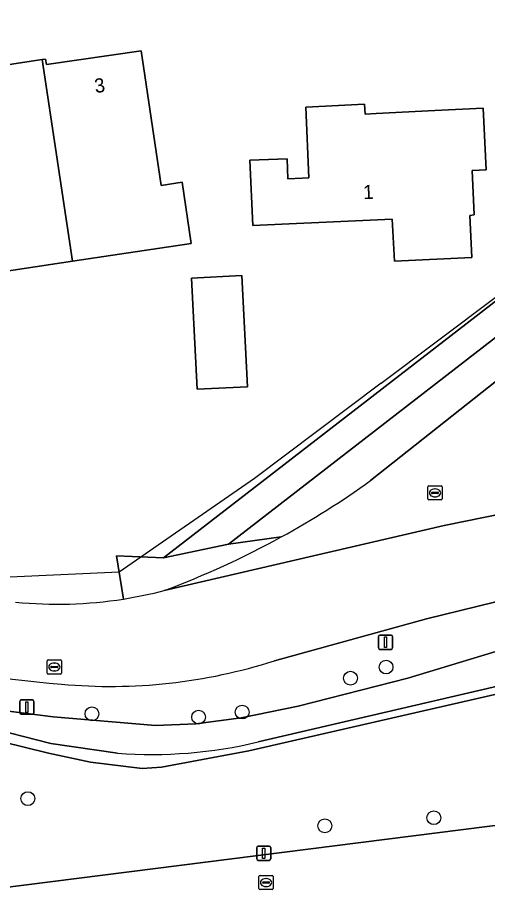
# Model space of a CAD drawing. Extents: x 162156 to 163172, y 378995 to 380779.
# Drawn here: x 162299.8 to 162333, y 380168.4 to 380231 of the extents above; entities that cross this region are included whole.
import ezdxf

# ---------------------------------------------------------------- set-up
doc = ezdxf.new("R2010")
doc.units = 0
for name, color, linetype in [('IMGEO_Boom', 7, 'Continuous'), ('IMGEO_Erf', 7, 'Continuous'), ('IMGEO_Groenvoorziening', 7, 'Continuous'), ('IMGEO_Hek', 7, 'Continuous'), ('IMGEO_Lichtmast', 7, 'Continuous'), ('IMGEO_Pand', 7, 'Continuous'), ('IMGEO_Pand_nummerreeks', 7, 'Continuous'), ('IMGEO_Rijbaan_lokaal_gesloten', 7, 'Continuous'), ('IMGEO_Rioolput', 7, 'Continuous'), ('IMGEO_Waterleidingput', 7, 'Continuous'), ('IMGEO_Waterloop', 7, 'Continuous')]:
    doc.layers.add(name, color=color, linetype=linetype)

msp = doc.modelspace()

# ---------------------------------------------------------------- linework, layer by layer
at = {"layer": 'IMGEO_Boom'}
for centre in [(162325.875, 380185.02), (162323.363, 380184.23), (162315.697, 380181.835), (162305.068, 380181.713), (162312.617, 380181.479), (162300.532, 380175.71), (162329.255, 380174.358), (162321.541, 380173.789)]:
    msp.add_circle(centre, 0.489, dxfattribs=at)
at = {"layer": 'IMGEO_Erf'}
for points in [[(162312.1, 380214.998), (162303.688, 380213.74), (162295.276, 380212.481), (162295.656, 380210.025), (162292.642, 380209.57), (162291.834, 380211.745), (162291.4, 380214.642), (162294.812, 380215.154), (162294.564, 380216.805), (162296.097, 380217.035), (162294.609, 380226.964), (162301.556, 380228.006), (162301.776, 380228.039), (162301.848, 380227.66), (162308.548, 380228.625), (162309.976, 380219.109), (162311.451, 380219.324)], [(162332.743, 380224.57), (162332.957, 380220.211), (162331.959, 380220.152), (162332.109, 380217.012), (162331.794, 380216.986), (162331.938, 380214.003), (162326.468, 380213.736), (162326.316, 380216.719), (162320.607, 380216.458), (162320.057, 380216.433), (162316.451, 380216.268), (162316.24, 380220.882), (162318.877, 380220.989), (162318.935, 380219.576), (162319.932, 380219.625), (162320.423, 380219.649), (162320.19, 380224.653), (162324.353, 380224.847), (162324.39, 380224.148), (162325.178, 380224.189), (162329.327, 380224.408)], [(162315.683, 380212.727), (162316.079, 380204.852), (162312.512, 380204.679), (162312.117, 380212.539)]]:
    msp.add_lwpolyline(points, close=True, dxfattribs=at)
msp.add_lwpolyline([(162307.295, 380189.835), (162306.81, 380192.901), (162310.127, 380192.76), (162353.115, 380225.997)], dxfattribs=at)
msp.add_arc((162302.622, 380219.443), 29.974, 264.33401, 278.96829, dxfattribs=at)
at = {"layer": 'IMGEO_Groenvoorziening'}
for points in [[(162354.159, 380226.783), (162353.115, 380225.997), (162310.127, 380192.76), (162314.733, 380193.715), (162354.477, 380224.489)], [(162354.477, 380224.489), (162314.733, 380193.715), (162318.467, 380194.227)], [(162324.772, 380198.212), (162340.006, 380210.284)], [(162318.467, 380194.227), (162314.733, 380193.715), (162310.127, 380192.76), (162306.81, 380192.901), (162307.295, 380189.835)], [(162408.085, 379703.181), (162408.289, 379704.226), (162408.362, 379710.922), (162407.433, 379718.658), (162402.674, 379750), (162400.562, 379766.602), (162399.53, 379777.438), (162398.595, 379783.512), (162394.073, 379815.929), (162388.914, 379854.445), (162387.247, 379866.948), (162383.975, 379890.989), (162369.543, 380000.044), (162352.327, 380129.869), (162352.7, 380129.905), (162350.587, 380145.671), (162344.822, 380188.69), (162344.718, 380189.464), (162342.565, 380189.181), (162342.118, 380191.718), (162328.735, 380188.436), (162317.977, 380185.472)], [(162289.203, 380186.217), (162277.89, 380189.107), (162278.442, 380184.1), (162278.772, 380184.135), (162278.757, 380184.272), (162292.3, 380181.3), (162302.003, 380178.939), (162304.976, 380178.29), (162308.611, 380177.854), (162309.981, 380177.927), (162316.172, 380179.083), (162342.217, 380185.053), (162346.322, 380153.311), (162346.539, 380151.632), (162347.441, 380145.205), (162349.391, 380131.315), (162352.731, 380105.568), (162366.947, 380000), (162368.464, 379988.666), (162368.623, 379987.477), (162371.684, 379964.606), (162386.534, 379853.639)], [(162306.872, 380178.924), (162302.171, 380179.61), (162297.351, 380180.835), (162290.271, 380182.222), (162278.755, 380184.863), (162279.04, 380186.519), (162289.844, 380183.552), (162297.843, 380182.07), (162302.338, 380181.506), (162309.559, 380180.888), (162312.416, 380181.003), (162315.635, 380181.426), (162319.666, 380182.264), (162327.408, 380184.242), (162341.185, 380188.417), (162341.57, 380185.476), (162316.835, 380179.72)]]:
    msp.add_lwpolyline(points, dxfattribs=at)
for points in [[(162338.626, 380174.447), (162341.504, 380153.008), (162346.322, 380153.311), (162342.217, 380185.053), (162316.172, 380179.083), (162309.981, 380177.927), (162308.611, 380177.854), (162304.976, 380178.29), (162302.003, 380178.939), (162292.3, 380181.3), (162278.757, 380184.272), (162278.772, 380184.135), (162280.517, 380167.715), (162235.526, 380161.77), (162231.086, 380161.186), (162231.132, 380160.825)], [(162347.875, 380105.55), (162341.504, 380153.008), (162338.626, 380174.447), (162231.132, 380160.825), (162234.006, 380138.54), (162234.545, 380138.605), (162235.45, 380138.742), (162239.5, 380111.988), (162238.595, 380111.851), (162237.47, 380111.681), (162239.093, 380099.095), (162240.095, 380091.317)]]:
    msp.add_lwpolyline(points, close=True, dxfattribs=at)
for centre, radius, start, end in [((162288.785, 380248.17), 61.57, 298.82183, 305.76706), ((162288.704, 380248.343), 61.76, 290.34479, 298.81046), ((162302.737, 380218.937), 29.456, 278.90108, 284.62756), ((162308.907, 380258.278), 74.706, 254.70699, 265.40243), ((162306.417, 380221.209), 37.56, 264.65655, 287.92526), ((162309.28, 380211.527), 32.692, 265.77515, 283.36081)]:
    msp.add_arc(centre, radius, start, end, dxfattribs=at)
at = {"layer": 'IMGEO_Hek'}
for points in [[(162325.53, 380205.107), (162353.989, 380226.515)], [(162325.53, 380205.107), (162316.565, 380198.358), (162306.984, 380191.725), (162299.257, 380191.374), (162294.601, 380191.534), (162271.637, 380197.316)], [(162342.217, 380185.053), (162316.172, 380179.083), (162309.981, 380177.927), (162308.611, 380177.854), (162304.976, 380178.29), (162302.003, 380178.939), (162292.3, 380181.3)]]:
    msp.add_lwpolyline(points, dxfattribs=at)
at = {"layer": 'IMGEO_Lichtmast'}
for p, q in [((162325.437, 380187.275), (162326.227, 380187.275)), ((162326.227, 380187.275), (162325.437, 380187.275)), ((162325.337, 380186.375), (162325.337, 380187.175)), ((162325.337, 380187.175), (162325.337, 380186.375)), ((162326.327, 380187.175), (162326.327, 380186.375)), ((162326.327, 380186.375), (162326.327, 380187.175)), ((162326.227, 380186.275), (162325.437, 380186.275)), ((162325.437, 380186.275), (162326.227, 380186.275)), ((162299.972, 380181.791), (162299.972, 380182.591)), ((162299.972, 380182.591), (162299.972, 380181.791)), ((162300.072, 380182.691), (162300.862, 380182.691)), ((162300.862, 380182.691), (162300.072, 380182.691)), ((162300.962, 380182.591), (162300.962, 380181.791)), ((162300.962, 380181.791), (162300.962, 380182.591)), ((162300.862, 380181.691), (162300.072, 380181.691)), ((162300.072, 380181.691), (162300.862, 380181.691)), ((162316.727, 380171.441), (162316.727, 380172.241)), ((162316.727, 380172.241), (162316.727, 380171.441)), ((162316.827, 380172.341), (162317.617, 380172.341)), ((162317.617, 380172.341), (162316.827, 380172.341)), ((162317.717, 380172.241), (162317.717, 380171.441)), ((162317.717, 380171.441), (162317.717, 380172.241)), ((162317.617, 380171.341), (162316.827, 380171.341)), ((162316.827, 380171.341), (162317.617, 380171.341))]:
    msp.add_line(p, q, dxfattribs=at)
for points in [[(162325.757, 380187.15), (162325.907, 380187.15), (162325.907, 380186.4), (162325.757, 380186.4), (162325.757, 380187.15)], [(162300.392, 380182.566), (162300.542, 380182.566), (162300.542, 380181.816), (162300.392, 380181.816), (162300.392, 380182.566)], [(162317.147, 380172.216), (162317.297, 380172.216), (162317.297, 380171.466), (162317.147, 380171.466), (162317.147, 380172.216)]]:
    msp.add_lwpolyline(points, dxfattribs=at)
for centre, start, end in [((162325.437, 380187.175), 90, 180), ((162325.437, 380187.175), 90, 180), ((162326.227, 380187.175), 0, 90), ((162326.227, 380187.175), 360, 90), ((162325.437, 380186.375), 180, 270), ((162325.437, 380186.375), 180, 270), ((162326.227, 380186.375), 270, 0), ((162326.227, 380186.375), 270, 0), ((162300.072, 380182.591), 90, 180), ((162300.072, 380182.591), 90, 180), ((162300.862, 380182.591), 0, 90), ((162300.862, 380182.591), 360, 90), ((162300.072, 380181.791), 180, 270), ((162300.072, 380181.791), 180, 270), ((162300.862, 380181.791), 270, 0), ((162300.862, 380181.791), 270, 0), ((162316.827, 380172.241), 90, 180), ((162316.827, 380172.241), 90, 180), ((162317.617, 380172.241), 0, 90), ((162317.617, 380172.241), 360, 90), ((162316.827, 380171.441), 180, 270), ((162316.827, 380171.441), 180, 270), ((162317.617, 380171.441), 270, 0), ((162317.617, 380171.441), 270, 0)]:
    msp.add_arc(centre, 0.1, start, end, dxfattribs=at)
at = {"layer": 'IMGEO_Pand'}
for points in [[(162301.556, 380228.006), (162303.688, 380213.74), (162312.1, 380214.998), (162311.451, 380219.324), (162309.976, 380219.109), (162308.548, 380228.625), (162301.848, 380227.66), (162301.776, 380228.039)], [(162301.556, 380228.006), (162294.609, 380226.964), (162296.097, 380217.035), (162294.564, 380216.805), (162294.812, 380215.154), (162291.4, 380214.642), (162291.834, 380211.745), (162292.642, 380209.57), (162295.656, 380210.025), (162295.276, 380212.481), (162303.688, 380213.74)], [(162331.959, 380220.152), (162332.957, 380220.211), (162332.743, 380224.57), (162329.327, 380224.408), (162325.178, 380224.189), (162324.39, 380224.148), (162324.353, 380224.847), (162320.19, 380224.653), (162320.423, 380219.649), (162319.932, 380219.625), (162318.935, 380219.576), (162318.877, 380220.989), (162316.24, 380220.882), (162316.451, 380216.268), (162320.057, 380216.433), (162320.607, 380216.458), (162326.316, 380216.719), (162326.468, 380213.736), (162331.938, 380214.003), (162331.794, 380216.986), (162332.109, 380217.012)], [(162315.683, 380212.727), (162312.117, 380212.539), (162312.512, 380204.679), (162316.079, 380204.852)]]:
    msp.add_lwpolyline(points, close=True, dxfattribs=at)
at = {"layer": 'IMGEO_Rijbaan_lokaal_gesloten'}
for points in [[(162381.999, 380241.493), (162372.733, 380234.326), (162366.037, 380229.487), (162365.645, 380229.204), (162358.695, 380224.728), (162358.331, 380224.494), (162353.288, 380221.289), (162343.433, 380213.084), (162340.006, 380210.284), (162324.772, 380198.212)], [(162310.176, 380190.435), (162329.976, 380195.039), (162345.414, 380198.175), (162349.145, 380198.355), (162351.924, 380198.488), (162350.331, 380198.596)], [(162419.663, 380191.175), (162393.262, 380193.962), (162392.976, 380193.997), (162382.958, 380195.235), (162353.196, 380198.402), (162351.924, 380198.488), (162349.145, 380198.355), (162345.414, 380198.175), (162329.976, 380195.039), (162310.176, 380190.435)], [(162317.977, 380185.472), (162328.735, 380188.436), (162342.118, 380191.718), (162342.53, 380191.819), (162342.628, 380191.832), (162342.726, 380191.844)]]:
    msp.add_lwpolyline(points, dxfattribs=at)
for centre, radius, start, end in [((162288.785, 380248.17), 61.57, 298.82183, 305.76706), ((162288.704, 380248.343), 61.76, 290.34479, 298.81046), ((162302.737, 380218.937), 29.456, 278.90108, 284.62756), ((162302.622, 380219.443), 29.974, 264.33401, 278.96829), ((162308.907, 380258.278), 74.706, 254.70699, 265.40243), ((162306.417, 380221.209), 37.56, 264.65655, 287.92526)]:
    msp.add_arc(centre, radius, start, end, dxfattribs=at)
at = {"layer": 'IMGEO_Rioolput'}
for p, q in [((162328.838, 380196.92), (162328.838, 380197.772)), ((162328.913, 380197.846), (162329.765, 380197.846)), ((162329.097, 380197.34), (162329.097, 380197.352)), ((162329.535, 380197.303), (162329.137, 380197.303)), ((162329.14, 380197.389), (162329.538, 380197.389)), ((162329.326, 380197.626), (162329.351, 380197.626)), ((162329.581, 380197.352), (162329.581, 380197.34)), ((162329.839, 380197.772), (162329.839, 380196.92)), ((162329.765, 380196.846), (162328.913, 380196.846)), ((162329.349, 380197.066), (162329.324, 380197.066)), ((162301.909, 380184.6), (162301.909, 380185.452)), ((162301.984, 380185.526), (162302.836, 380185.526)), ((162302.91, 380185.452), (162302.91, 380184.6)), ((162302.168, 380185.02), (162302.168, 380185.032)), ((162302.606, 380184.983), (162302.208, 380184.983)), ((162302.211, 380185.069), (162302.609, 380185.069)), ((162302.42, 380184.746), (162302.395, 380184.746)), ((162302.397, 380185.306), (162302.422, 380185.306)), ((162302.652, 380185.032), (162302.652, 380185.02)), ((162302.836, 380184.526), (162301.984, 380184.526))]:
    msp.add_line(p, q, dxfattribs=at)
for points in [[(162328.838, 380196.92), (162328.838, 380197.772)], [(162328.913, 380197.846), (162329.765, 380197.846)], [(162329.839, 380197.772), (162329.839, 380196.92)], [(162329.765, 380196.846), (162328.913, 380196.846)], [(162301.909, 380184.6), (162301.909, 380185.452)], [(162301.984, 380185.526), (162302.836, 380185.526)], [(162302.91, 380185.452), (162302.91, 380184.6)], [(162302.836, 380184.526), (162301.984, 380184.526)]]:
    msp.add_lwpolyline(points, dxfattribs=at)
for centre, radius, start, end in [((162328.915, 380197.77), 0.0765, 91.55205, 178.44795), ((162328.915, 380197.77), 0.0765, 91.55205, 178.44795), ((162329.137, 380197.349), 0.0403, 85.87752, 175.75265), ((162329.134, 380197.339), 0.0366, 178.93798, 274.71019), ((162329.538, 380197.346), 0.043, 264.86636, 352.45326), ((162329.542, 380197.351), 0.0386, 1.73085, 96.63898), ((162329.763, 380197.77), 0.0765, 1.55205, 88.44795), ((162329.763, 380197.77), 0.0765, 1.55205, 88.44795), ((162328.915, 380196.922), 0.0765, 181.55205, 268.44795), ((162328.915, 380196.922), 0.0765, 181.55205, 268.44795), ((162329.763, 380196.922), 0.0765, 271.55205, 358.44795), ((162329.763, 380196.922), 0.0765, 271.55205, 358.44795), ((162301.986, 380185.45), 0.0765, 91.55205, 178.44795), ((162301.986, 380185.45), 0.0765, 91.55205, 178.44795), ((162302.834, 380185.45), 0.0765, 1.55205, 88.44795), ((162302.834, 380185.45), 0.0765, 1.55205, 88.44795), ((162302.208, 380185.029), 0.0403, 85.87752, 175.75265), ((162302.205, 380185.019), 0.0366, 178.93798, 274.71019), ((162302.609, 380185.026), 0.043, 264.86636, 352.45326), ((162302.613, 380185.031), 0.0386, 1.73085, 96.63898), ((162301.986, 380184.602), 0.0765, 181.55205, 268.44795), ((162301.986, 380184.602), 0.0765, 181.55205, 268.44795), ((162302.834, 380184.602), 0.0765, 271.55205, 358.44795), ((162302.834, 380184.602), 0.0765, 271.55205, 358.44795)]:
    msp.add_arc(centre, radius, start, end, dxfattribs=at)
for centre, major_axis, ratio, start_param, end_param in [((162329.325, 380197.346), (-0.387, 0.002), 0.722429, 4.712389, 7.853982), ((162329.35, 380197.346), (-0.39, 0.002), 0.717154, 1.570796, 4.712389), ((162302.396, 380185.026), (-0.387, 0.002), 0.722429, 4.712389, 7.853982), ((162302.421, 380185.026), (-0.39, 0.002), 0.717154, 1.570796, 4.712389)]:
    msp.add_ellipse(centre, major_axis=major_axis, ratio=ratio, start_param=start_param, end_param=end_param, dxfattribs=at)
at = {"layer": 'IMGEO_Waterleidingput'}
for p, q in [((162316.886, 380169.344), (162316.886, 380170.196)), ((162316.961, 380170.27), (162317.813, 380170.27)), ((162317.145, 380169.764), (162317.145, 380169.776)), ((162317.583, 380169.727), (162317.185, 380169.727)), ((162317.188, 380169.813), (162317.586, 380169.813)), ((162317.374, 380170.05), (162317.399, 380170.05)), ((162317.629, 380169.776), (162317.629, 380169.764)), ((162317.887, 380170.196), (162317.887, 380169.344)), ((162317.813, 380169.27), (162316.961, 380169.27)), ((162317.397, 380169.49), (162317.372, 380169.49))]:
    msp.add_line(p, q, dxfattribs=at)
for points in [[(162316.886, 380169.344), (162316.886, 380170.196)], [(162316.961, 380170.27), (162317.813, 380170.27)], [(162317.887, 380170.196), (162317.887, 380169.344)], [(162317.813, 380169.27), (162316.961, 380169.27)]]:
    msp.add_lwpolyline(points, dxfattribs=at)
for centre, radius, start, end in [((162316.963, 380170.194), 0.0765, 91.55205, 178.44795), ((162316.963, 380170.194), 0.0765, 91.55205, 178.44795), ((162317.185, 380169.773), 0.0403, 85.87752, 175.75265), ((162317.182, 380169.763), 0.0366, 178.93798, 274.71019), ((162317.586, 380169.77), 0.043, 264.86636, 352.45326), ((162317.59, 380169.775), 0.0386, 1.73085, 96.63898), ((162317.811, 380170.194), 0.0765, 1.55205, 88.44795), ((162317.811, 380170.194), 0.0765, 1.55205, 88.44795), ((162316.963, 380169.346), 0.0765, 181.55205, 268.44795), ((162316.963, 380169.346), 0.0765, 181.55205, 268.44795), ((162317.811, 380169.346), 0.0765, 271.55205, 358.44795), ((162317.811, 380169.346), 0.0765, 271.55205, 358.44795)]:
    msp.add_arc(centre, radius, start, end, dxfattribs=at)
for centre, major_axis, ratio, start_param, end_param in [((162317.373, 380169.77), (-0.387, 0.002), 0.722429, 4.712389, 7.853982), ((162317.398, 380169.77), (-0.39, 0.002), 0.717154, 1.570796, 4.712389)]:
    msp.add_ellipse(centre, major_axis=major_axis, ratio=ratio, start_param=start_param, end_param=end_param, dxfattribs=at)
at = {"layer": 'IMGEO_Waterloop'}
msp.add_lwpolyline([(162316.835, 380179.72), (162341.57, 380185.476), (162341.185, 380188.417), (162327.408, 380184.242), (162319.666, 380182.264), (162315.635, 380181.426), (162312.416, 380181.003), (162309.559, 380180.888), (162302.338, 380181.506), (162297.843, 380182.07), (162289.844, 380183.552), (162279.04, 380186.519), (162278.755, 380184.863), (162290.271, 380182.222), (162297.351, 380180.835), (162302.171, 380179.61), (162306.872, 380178.924)], dxfattribs=at)
msp.add_arc((162309.28, 380211.527), 32.692, 265.77515, 283.36081, dxfattribs=at)

# ---------------------------------------------------------------- texts
at = {"layer": 'IMGEO_Pand_nummerreeks'}
for s, rotation, p in [('3', 8.1933, (162305.317, 380225.634)), ('1', 2.41788, (162324.274, 380218.128))]:
    msp.add_text(s, height=1, rotation=rotation, dxfattribs=at).set_placement(p)

doc.saveas('drawing.dxf')
